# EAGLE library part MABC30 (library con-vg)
Male Connector C/3, 30 Solder DIN EN 60 603-02 Source: www.erni.com .. 424189.pdf
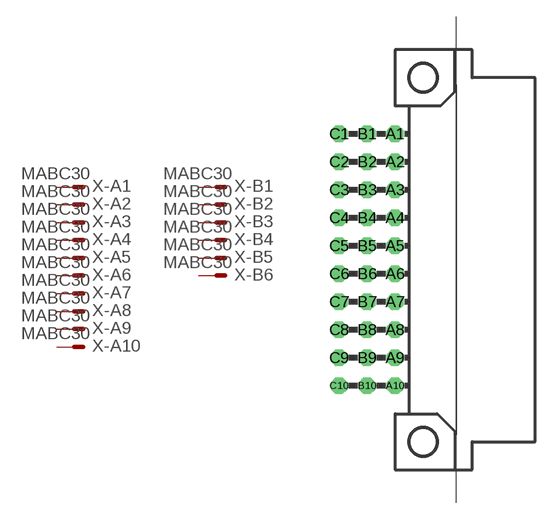
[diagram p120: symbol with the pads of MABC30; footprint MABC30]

Designator prefix X; gates -A1=MVAL -A2=MVAL -A3=MVAL -A4=MVAL -A5=MVAL -A6=MVAL -A7=MVAL -A8=MVAL -A9=MVAL -A10=MVAL -B1=MVAL -B2=MVAL -B3=MVAL -B4=MVAL -B5=MVAL -B6=MVAL -B7=MVAL -B8=MVAL -B9=MVAL -B10=MVAL -C1=MVAL -C2=MVAL -C3=MVAL -C4=MVAL -C5=MVAL -C6=MVAL -C7=MVAL -C8=MVAL -C9=MVAL -C10=MVAL

## MABC30  [MABC30]
A1  -A1:S  pas
A2  -A2:S  pas
A3  -A3:S  pas
A4  -A4:S  pas
A5  -A5:S  pas
A6  -A6:S  pas
A7  -A7:S  pas
A8  -A8:S  pas
A9  -A9:S  pas
A10  -A10:S  pas
B1  -B1:S  pas
B2  -B2:S  pas
B3  -B3:S  pas
B4  -B4:S  pas
B5  -B5:S  pas
B6  -B6:S  pas
B7  -B7:S  pas
B8  -B8:S  pas
B9  -B9:S  pas
B10  -B10:S  pas
C1  -C1:S  pas
C2  -C2:S  pas
C3  -C3:S  pas
C4  -C4:S  pas
C5  -C5:S  pas
C6  -C6:S  pas
C7  -C7:S  pas
C8  -C8:S  pas
C9  -C9:S  pas
C10  -C10:S  pas

## Footprint MABC30 (pad centres in mm)
Male Connector C/3, 30 Solder Source: www.erni.com .. 424189.pdf
drill 1.016 pad 1.5 octagon: A1 0,11.43; A2 0,8.89; A3 0,6.35; A4 0,3.81; A5 0,1.27; A6 0,-1.27; A7 0,-3.81; A8 0,-6.35; A9 0,-8.89; A10 0,-11.43; B1 -2.54,11.43; B2 -2.54,8.89; B3 -2.54,6.35; B4 -2.54,3.81; B5 -2.54,1.27; B6 -2.54,-1.27; B7 -2.54,-3.81; B8 -2.54,-6.35; B9 -2.54,-8.89; B10 -2.54,-11.43; C1 -5.08,11.43; C2 -5.08,8.89; C3 -5.08,6.35; C4 -5.08,3.81; C5 -5.08,1.27; C6 -5.08,-1.27; C7 -5.08,-3.81; C8 -5.08,-6.35; C9 -5.08,-8.89; C10 -5.08,-11.43
hole 2.794 at 2.54,16.51
hole 2.794 at 2.54,-16.51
